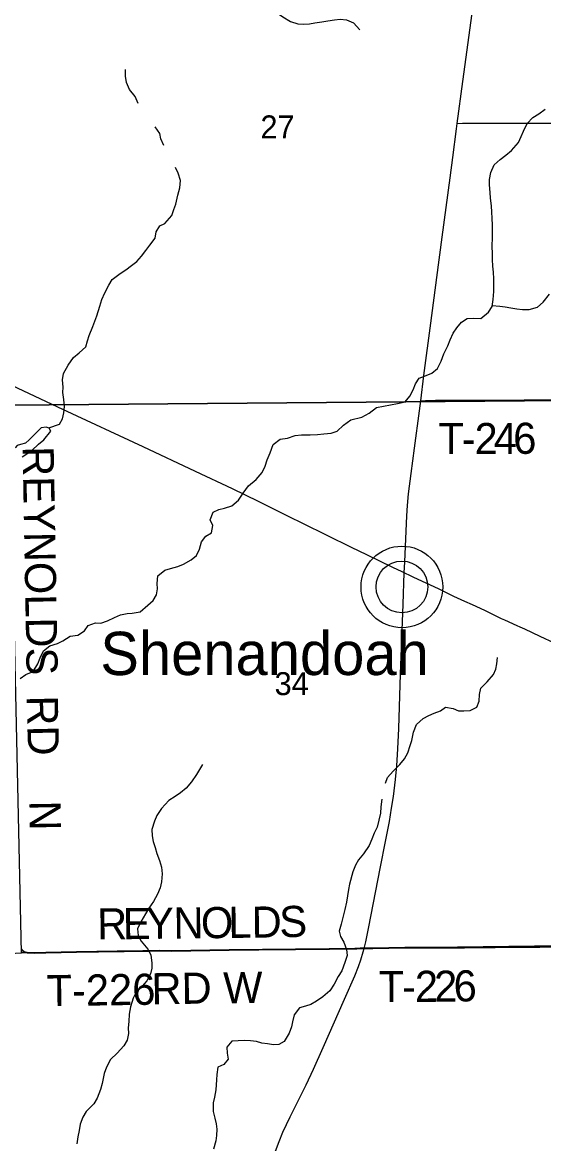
# Model space of a CAD drawing. Extents: x 0 to 34, y 0 to 22.
# Drawn here: x 2.445 to 3.396, y 17.915 to 19.961 of the extents above; entities that cross this region are included whole.
import ezdxf

# ---------------------------------------------------------------- set-up
doc = ezdxf.new("R2010")
doc.units = 0
for name, color, linetype in [('Default', 7, 'Continuous'), ('GM_X_Minor_Lake', 7, 'Continuous'), ('GM_X_Minor_River', 7, 'Continuous'), ('GM_X_Section', 7, 'Continuous'), ('GM_X_Section_Text', 7, 'Continuous'), ('GM_X_State_Route', 7, 'Continuous'), ('GM_X_Township_Road', 7, 'Continuous'), ('GM_X_Township_Road_Text', 7, 'Continuous'), ('GM_X_Unincorporated', 7, 'Continuous'), ('GM_X_Unincorporated_Location', 7, 'Continuous'), ('GM_X_Unincorporated_Text', 7, 'Continuous')]:
    doc.layers.add(name, color=color, linetype=linetype)

msp = doc.modelspace()

# ---------------------------------------------------------------- linework, layer by layer
at = {"layer": 'Default'}
for points in [[(3.4301, 18.2744), (3.3888, 18.2738), (3.3073, 18.2728), (3.2514, 18.2724), (3.1924, 18.2724), (3.1428, 18.2723), (3.0843, 18.2713), (3.0681, 18.2714), (3.0612, 18.2711), (3.0546, 18.271), (3.0053, 18.2702), (2.9434, 18.2695), (2.8221, 18.2683), (2.7172, 18.2666), (2.6957, 18.2668), (2.6647, 18.2662), (2.6182, 18.2656), (2.5438, 18.2646), (2.488, 18.2636), (2.4663, 18.2631), (2.46, 18.2631), (2.4539, 18.2636), (2.4509, 18.2643), (2.4481, 18.2655), (2.4455, 18.2673), (2.4435, 18.2696)], [(2.4435, 18.2696), (2.4455, 18.2673), (2.4481, 18.2655), (2.4509, 18.2643), (2.4539, 18.2636), (2.46, 18.2631), (2.4663, 18.2631), (2.488, 18.2636), (2.5438, 18.2646), (2.6182, 18.2656), (2.6647, 18.2662), (2.6957, 18.2668), (2.7172, 18.2666), (2.8221, 18.2683), (2.9434, 18.2695), (3.0053, 18.2702), (3.0546, 18.271), (3.0612, 18.2711), (3.0681, 18.2714), (3.0843, 18.2713), (3.1428, 18.2723), (3.1924, 18.2724), (3.2514, 18.2724), (3.3073, 18.2728), (3.3888, 18.2738), (3.4301, 18.2744)]]:
    msp.add_lwpolyline(points, dxfattribs=at)
at = {"layer": 'GM_X_Minor_Lake'}
msp.add_lwpolyline([(2.445, 19.1677), (2.4622, 19.1792), (2.4749, 19.1909), (2.4841, 19.1991), (2.4971, 19.2145), (2.4942, 19.2203), (2.4885, 19.2222), (2.4794, 19.2208), (2.4671, 19.2084), (2.4575, 19.199), (2.451, 19.193), (2.4415, 19.1905), (2.4357, 19.1887), (2.4319, 19.1841)], dxfattribs=at)
at = {"layer": 'GM_X_Minor_River'}
for points in [[(2.8893, 20.0305), (2.8971, 20.0168), (2.9027, 20.0034), (2.9033, 19.989), (2.9085, 19.9787), (2.9205, 19.9706), (2.9345, 19.9624), (2.9477, 19.9581), (2.9587, 19.9576), (2.9686, 19.9582), (2.9785, 19.9596), (2.9914, 19.9614), (3.0021, 19.9632), (3.0146, 19.9653), (3.0245, 19.9663), (3.0366, 19.9651), (3.0491, 19.96), (3.0607, 19.9473)], [(2.6564, 19.8126), (2.6509, 19.8252), (2.6404, 19.8382), (2.6352, 19.8508), (2.6334, 19.8622), (2.6332, 19.8744)], [(3.091, 19.2578), (3.1293, 19.2651), (3.1434, 19.2681), (3.1518, 19.2783), (3.1579, 19.2904), (3.1621, 19.301), (3.1686, 19.3113), (3.1819, 19.3165), (3.1922, 19.3206), (3.2021, 19.3293), (3.209, 19.3422), (3.214, 19.3558), (3.2209, 19.3706), (3.2255, 19.3812), (3.2309, 19.3937), (3.2374, 19.4035), (3.2458, 19.4138), (3.2564, 19.4205), (3.2686, 19.4212), (3.2815, 19.4204), (3.2956, 19.4317), (3.3017, 19.4423), (3.304, 19.4548), (3.3052, 19.4693), (3.3053, 19.4924), (3.3046, 19.5046), (3.3035, 19.5156), (3.3028, 19.5277), (3.3025, 19.5384), (3.3022, 19.552), (3.3027, 19.5683), (3.3028, 19.5907), (3.3021, 19.6033), (3.3014, 19.6143), (3.3007, 19.626), (3.2988, 19.6397), (3.2985, 19.6503), (3.297, 19.664), (3.2971, 19.6739), (3.2994, 19.6864), (3.3056, 19.7004), (3.3166, 19.7102), (3.3269, 19.7182), (3.3372, 19.7268), (3.3498, 19.7412), (3.3551, 19.7522), (3.3594, 19.7624), (3.3659, 19.7764), (3.3762, 19.787), (3.3872, 19.7938), (3.3986, 19.8024)], [(2.7034, 19.7358), (2.6979, 19.7484), (2.6957, 19.7579), (2.6871, 19.7701)], [(2.4934, 19.2205), (2.5132, 19.2276), (2.5183, 19.2375), (2.5211, 19.2481), (2.5223, 19.2598), (2.5206, 19.2727), (2.5192, 19.2853), (2.5193, 19.2948), (2.5183, 19.3085), (2.5203, 19.3202), (2.5285, 19.3353), (2.5385, 19.3489), (2.5485, 19.3579), (2.5607, 19.3687), (2.5639, 19.3793), (2.5671, 19.3895), (2.5737, 19.4054), (2.5776, 19.4152), (2.5811, 19.4251), (2.5862, 19.4429), (2.5902, 19.455), (2.5956, 19.4674), (2.6026, 19.4814), (2.6088, 19.4912), (2.6234, 19.5024), (2.6341, 19.5091), (2.6444, 19.517), (2.654, 19.5245), (2.6624, 19.5342), (2.6705, 19.5444), (2.6775, 19.5542), (2.6875, 19.5666), (2.6891, 19.5784), (2.6957, 19.5893), (2.7052, 19.5937), (2.7176, 19.6084), (2.7215, 19.619), (2.725, 19.6288), (2.729, 19.6455), (2.7325, 19.6587), (2.7334, 19.672), (2.7294, 19.6857), (2.7242, 19.6957)], [(3.302, 19.4438), (3.3161, 19.4426), (3.3256, 19.4418), (3.3362, 19.4399), (3.3472, 19.4379), (3.3574, 19.4367), (3.3692, 19.4367), (3.3844, 19.4408), (3.3951, 19.4502), (3.4065, 19.4646)], [(2.6914, 18.9268), (2.6911, 18.937), (2.6924, 18.9507), (2.705, 18.9608), (2.7153, 18.9641), (2.729, 18.9677), (2.7389, 18.9718), (2.7531, 18.98), (2.763, 18.9878), (2.7685, 18.9995), (2.7717, 19.0128), (2.7797, 19.023), (2.7901, 19.0293), (2.7925, 19.0425), (2.7877, 19.0529), (2.7931, 19.0668), (2.8034, 19.0717), (2.8137, 19.0742), (2.8274, 19.0786), (2.8393, 19.0891), (2.8478, 19.1015), (2.8578, 19.1147), (2.8713, 19.1267), (2.8828, 19.1395), (2.8878, 19.1508), (2.8914, 19.1622), (2.8969, 19.1754), (2.9027, 19.1901), (2.9153, 19.1999), (2.9287, 19.202), (2.9428, 19.2068), (2.9545, 19.2081), (2.9701, 19.208), (2.9834, 19.2086), (2.9952, 19.2096), (3.0081, 19.2109), (3.0192, 19.2146), (3.0307, 19.2259), (3.0441, 19.2352), (3.0646, 19.2403), (3.0776, 19.2477), (3.091, 19.2578)], [(2.4409, 18.7633), (2.4512, 18.7708), (2.4649, 18.7759), (2.4731, 18.7903), (2.4777, 18.8012), (2.4836, 18.8137), (2.4951, 18.8231), (2.5092, 18.8275), (2.5187, 18.8323), (2.5325, 18.8409), (2.5462, 18.8426), (2.5584, 18.8501), (2.5653, 18.8599), (2.5787, 18.865), (2.5885, 18.8645), (2.6007, 18.8686), (2.613, 18.8749), (2.624, 18.8797), (2.6362, 18.8822), (2.6457, 18.8825), (2.6601, 18.885), (2.6739, 18.897), (2.6839, 18.906), (2.6901, 18.9158), (2.6914, 18.9268)], [(3.1074, 18.5725), (3.1113, 18.5827), (3.1212, 18.5945), (3.1334, 18.6062), (3.1422, 18.6167), (3.1479, 18.6277), (3.1525, 18.641), (3.1552, 18.6505), (3.1583, 18.6656), (3.1641, 18.6797), (3.1759, 18.6902), (3.1862, 18.6962), (3.1964, 18.7), (3.2075, 18.7045), (3.217, 18.7113), (3.231, 18.7086), (3.2409, 18.7047), (3.2503, 18.7043), (3.2621, 18.705), (3.2743, 18.7114), (3.2785, 18.722), (3.2789, 18.7345), (3.2813, 18.7459), (3.2927, 18.7576), (3.3045, 18.7705), (3.3088, 18.7803), (3.3107, 18.7902), (3.3119, 18.8019)], [(2.774, 18.6065), (2.7628, 18.588), (2.7535, 18.5748), (2.7439, 18.5631), (2.7335, 18.5545), (2.7236, 18.5482), (2.7121, 18.5407), (2.699, 18.5261), (2.6906, 18.5136), (2.6859, 18.503), (2.6815, 18.4879), (2.6818, 18.4765), (2.6836, 18.4659), (2.6872, 18.4548), (2.6905, 18.4438), (2.6953, 18.4312), (2.699, 18.4194), (2.7004, 18.4068), (2.6991, 18.3924), (2.6963, 18.3814), (2.6916, 18.3697), (2.6843, 18.3565), (2.6758, 18.3441), (2.67, 18.3343), (2.6611, 18.3195), (2.6552, 18.3067), (2.6562, 18.2945), (2.6618, 18.2842), (2.6742, 18.2697), (2.6794, 18.259), (2.6815, 18.2441), (2.681, 18.2346), (2.6786, 18.2244), (2.6724, 18.2116), (2.6636, 18.2018), (2.6524, 18.1898), (2.647, 18.18), (2.6426, 18.1644), (2.6402, 18.1512), (2.6393, 18.1375), (2.6384, 18.1261), (2.6387, 18.1155), (2.6363, 18.1034), (2.6305, 18.0932), (2.6182, 18.0797), (2.6059, 18.068), (2.5989, 18.0541), (2.5942, 18.0427), (2.5906, 18.0242), (2.5878, 18.0136), (2.5816, 17.9977), (2.5754, 17.9871), (2.5615, 17.9736), (2.5554, 17.9631), (2.5507, 17.9502), (2.5486, 17.9385), (2.5466, 17.9271), (2.5446, 17.9142)], [(3.1005, 18.5431), (3.0992, 18.5294), (3.0983, 18.5177), (3.0955, 18.5048), (3.092, 18.4919), (3.0865, 18.4814), (3.0826, 18.47), (3.0779, 18.4587), (3.0675, 18.4436), (3.0583, 18.4327), (3.0525, 18.4229), (3.0478, 18.4108), (3.0415, 18.3881), (3.0398, 18.3782), (3.0382, 18.3669), (3.0362, 18.3551), (3.0334, 18.3422), (3.029, 18.3248), (3.0266, 18.315), (3.023, 18.3025), (3.0256, 18.2926), (3.0312, 18.2823), (3.0363, 18.2689), (3.0377, 18.2579), (3.0334, 18.245), (3.0279, 18.2303), (3.0214, 18.2197), (3.0136, 18.2058), (3.0059, 18.1937), (2.9929, 18.1825), (2.9814, 18.1746), (2.9711, 18.1687), (2.9615, 18.1653), (2.9505, 18.1624), (2.9409, 18.15), (2.9377, 18.1371), (2.9361, 18.1277), (2.9318, 18.1163), (2.9225, 18.1012), (2.9129, 18.0953), (2.9031, 18.095), (2.8921, 18.097), (2.8822, 18.0983), (2.8724, 18.1011), (2.8614, 18.1023), (2.8511, 18.1028), (2.839, 18.1022), (2.8272, 18.1016), (2.818, 18.091), (2.8186, 18.08), (2.8208, 18.069), (2.8127, 18.0592), (2.8016, 18.054), (2.7996, 18.0408), (2.7995, 18.0309), (2.7981, 18.0131), (2.7953, 17.9994), (2.7929, 17.9892), (2.7931, 17.9736), (2.7964, 17.961), (2.7989, 17.9508), (2.7996, 17.9413), (2.7991, 17.9295), (2.7978, 17.92), (2.7939, 17.9045)]]:
    msp.add_lwpolyline(points, dxfattribs=at)
at = {"layer": 'GM_X_Section'}
for points in [[(3.4017, 20.2979), (3.4336, 19.2705), (2.4218, 19.2622), (2.3914, 20.2927)], [(3.4336, 19.2705), (3.4536, 18.2761), (3.4263, 18.2757), (2.4434, 18.2628), (2.4218, 19.2622)], [(2.4116, 18.261), (2.4434, 18.2628), (3.4263, 18.2757), (3.4308, 17.2748), (2.406, 17.2639)]]:
    msp.add_lwpolyline(points, close=True, dxfattribs=at)
at = {"layer": 'GM_X_State_Route'}
msp.add_line((3.4456, 18.8137), (3.3898, 18.8402), dxfattribs=at)
for points in [[(3.0684, 18.2709), (3.0713, 18.2827), (3.0765, 18.307), (3.0984, 18.4199), (3.1072, 18.4657), (3.1145, 18.5023), (3.1187, 18.5268), (3.1219, 18.5483), (3.1256, 18.5791), (3.1279, 18.6038), (3.13, 18.6348), (3.1317, 18.672), (3.135, 18.7714), (3.1397, 18.8988), (3.1418, 18.9563), (3.1425, 18.9764), (3.1461, 19.0603), (3.1473, 19.0789), (3.1495, 19.1006), (3.1542, 19.1376), (3.1603, 19.1838), (3.1692, 19.2516), (3.1716, 19.2703), (3.1776, 19.3163), (3.1904, 19.4119), (3.2012, 19.495), (3.2109, 19.569), (3.2251, 19.6769), (3.2302, 19.7138), (3.237, 19.7662), (3.2383, 19.7764), (3.2482, 19.8525), (3.2674, 19.991)], [(3.1418, 18.9563), (3.138, 18.958), (3.1211, 18.9659), (3.0737, 18.9891), (3.0457, 19.0023), (2.9565, 19.0463), (2.9315, 19.0586), (2.876, 19.0866), (2.8284, 19.1093), (2.761, 19.141), (2.6657, 19.1863), (2.519, 19.2541), (2.4376, 19.2927), (2.4238, 19.2998), (2.4221, 19.3007), (2.4075, 19.3089), (2.3888, 19.32), (2.373, 19.3301), (2.3552, 19.3426), (2.3226, 19.3665), (2.2499, 19.4197), (2.1851, 19.468), (2.1405, 19.5017), (2.1, 19.533)], [(3.3898, 18.8402), (3.3618, 18.8534), (3.3533, 18.8571), (3.3475, 18.8594), (3.3249, 18.8696), (3.3193, 18.8723), (3.3163, 18.8734), (3.2886, 18.8873), (3.2662, 18.8977), (3.252, 18.904), (3.2323, 18.9132), (3.2044, 18.9268), (3.1593, 18.9478), (3.1543, 18.9501), (3.1418, 18.9563)], [(2.8645, 17.7422), (2.8715, 17.7718), (2.8744, 17.7841), (2.8809, 17.8113), (2.8866, 17.8355), (2.8933, 17.8595), (2.8997, 17.8803), (2.9068, 17.9009), (2.9134, 17.9184), (2.9205, 17.9356), (2.9338, 17.9637), (2.9628, 18.0222), (2.976, 18.0503), (2.9938, 18.09), (3.0325, 18.1783), (3.0513, 18.2209), (3.0583, 18.2381), (3.0624, 18.2498), (3.0668, 18.2647), (3.0684, 18.2709)]]:
    msp.add_lwpolyline(points, dxfattribs=at)
at = {"layer": 'GM_X_Township_Road'}
for points in [[(3.2383, 19.7764), (3.2479, 19.7766), (3.2634, 19.7769), (3.3877, 19.777), (3.4187, 19.7769)], [(3.1716, 19.2703), (3.1803, 19.2705), (3.1989, 19.2711), (3.2331, 19.2711), (3.2952, 19.2714), (3.3605, 19.2717), (3.4338, 19.2725)], [(2.4437, 18.269), (2.4458, 18.2667), (2.4483, 18.265), (2.4511, 18.2638), (2.4541, 18.2631), (2.4603, 18.2626), (2.4665, 18.2625), (2.4882, 18.2631), (2.544, 18.2641), (2.6184, 18.265), (2.6649, 18.2656), (2.6959, 18.2662), (2.7174, 18.266), (2.8223, 18.2678), (2.9306, 18.2688)], [(2.9306, 18.2688), (2.9436, 18.2689), (3.0056, 18.2697), (3.0549, 18.2704), (3.0614, 18.2706), (3.0684, 18.2709)], [(3.0684, 18.2709), (3.0845, 18.2708), (3.143, 18.2718), (3.1927, 18.2718), (3.2516, 18.2718), (3.3075, 18.2723), (3.389, 18.2733), (3.4303, 18.2739)]]:
    msp.add_lwpolyline(points, dxfattribs=at)
at = {"layer": 'GM_X_Unincorporated'}
for radius in [0.0744, 0.0472]:
    msp.add_circle((3.1374, 18.9305), radius, dxfattribs=at)
at = {"layer": 'GM_X_Unincorporated_Location'}
msp.add_line((3.1374, 18.9305), (3.1374, 18.9305), dxfattribs=at)

# ---------------------------------------------------------------- texts
at = {"layer": 'GM_X_Section_Text'}
for s, p in [('27', (2.8794, 19.749)), ('34', (2.9052, 18.7331))]:
    msp.add_text(s, height=0.04186, rotation=0, dxfattribs=at).set_placement(p)
at = {"layer": 'GM_X_Township_Road_Text'}
for s, height, rotation, p in [('2', 0.0568, 0.0477, (3.2699, 19.1728)), ('6', 0.0568, 0.9562, (3.3408, 19.173)), ('T', 0.0568, 0, (3.204, 19.1728)), ('4', 0.0568, 0.2057, (3.305, 19.1728)), ('-', 0.0568, 0.0086, (3.2465, 19.1728)), ('REYNOLDS', 0.05682, 271.0272, (2.4455, 19.1868)), ('RD', 0.05682, 271.3366, (2.453, 18.7318)), ('N', 0.0568, 270.9394, (2.458, 18.5403)), ('R', 0.0568, 0.6596, (2.5819, 18.2871)), ('E', 0.0568, 0.6615, (2.6286, 18.2876)), ('Y', 0.0568, 0.6593, (2.6711, 18.2881)), ('N', 0.0568, 0.6593, (2.7211, 18.2887)), ('O', 0.0568, 0.6609, (2.7711, 18.2893)), ('L', 0.0568, 0.66, (2.8211, 18.2899)), ('D', 0.0568, 0.6796, (2.8636, 18.2904)), ('S', 0.0568, 1.5237, (2.9145, 18.291)), ('RD W', 0.05682, 0.793, (2.681, 18.1688)), ('T', 0.0568, 0.3043, (3.0953, 18.1728)), ('2', 0.0568, 0.3569, (3.1612, 18.1732)), ('2', 0.0568, 0.51, (3.1964, 18.1734)), ('6', 0.0568, 1.253, (3.2322, 18.1737)), ('T-226', 0.05682, 0.8502, (2.4897, 18.1653)), ('-', 0.0568, 0.3148, (3.1378, 18.173))]:
    msp.add_text(s, height=height, rotation=rotation, dxfattribs=at).set_placement(p)
at = {"layer": 'GM_X_Unincorporated_Text'}
msp.add_text('Shenandoah', height=0.07898, rotation=0, dxfattribs=at).set_placement((2.5873, 18.7697))

doc.saveas('drawing.dxf')
